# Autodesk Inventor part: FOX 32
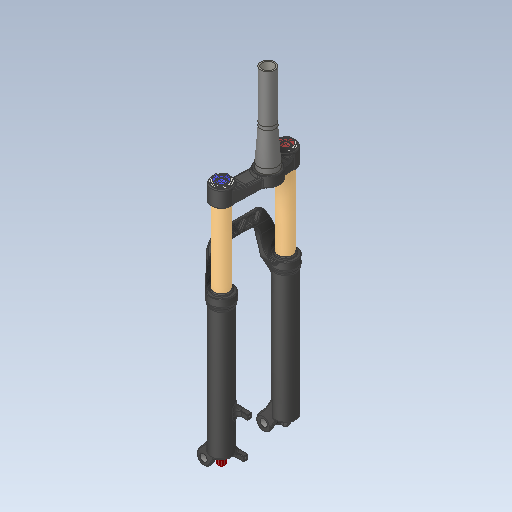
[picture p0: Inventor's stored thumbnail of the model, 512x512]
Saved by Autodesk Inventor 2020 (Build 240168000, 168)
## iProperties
Created: 2017-09
Part Number: FOX 32
Material: Ogólny
Document SubType Name: Modeling
Designer: Tomasz
Density: 1 g/cm^3
Appearance: Domyślna
Sending System: SolidWorks 2017
Last Author: Tomasz
Last Saved: 2017-11-20
Author: Tomasz
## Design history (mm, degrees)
feature "fox 32.CATPart[2]" [Extrude]
feature "fox 32.CATPart[3]" [Extrude]
feature "Extrude1"
node "Bryła1"
node "Bryła2"
node "Bryła3"
